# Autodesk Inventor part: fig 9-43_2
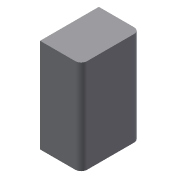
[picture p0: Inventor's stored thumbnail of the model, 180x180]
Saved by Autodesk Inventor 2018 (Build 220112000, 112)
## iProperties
Created: 2013-03
Part Number: fig 9-43_2
Material: Generic
Document SubType Name: Modeling
Designer: CADCIM
Density: 1 g/cm^3
Appearance: Default
Author: CADCIM
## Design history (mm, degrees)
sketch "Sketch1"
  geometry: L1 (-2.508, 1.862)-(2.492, 1.862); L2 (2.492, 1.862)-(2.492, -6.138); L3 (2.492, -6.138)-(-2.508, -6.138); L4 (-2.508, -6.138)-(-2.508, 1.862); 1 further point
  constraints: 8 end point, 2 parallel, 1 horizontal, 1 perpendicular
  dimensions: "d0" = 5 distance of L1.start L1.end; "d2" = 8 distance of L1.end L2.end
extrude "Extrusion1" new body sketch "Sketch1" distance "d3" = 3.5; taper "d4" = 0 deg
fillet "Fillet1" dims "d5" = 0.5
fillet "Fillet2" dims "d6" = 0.5
body "Solid1"
